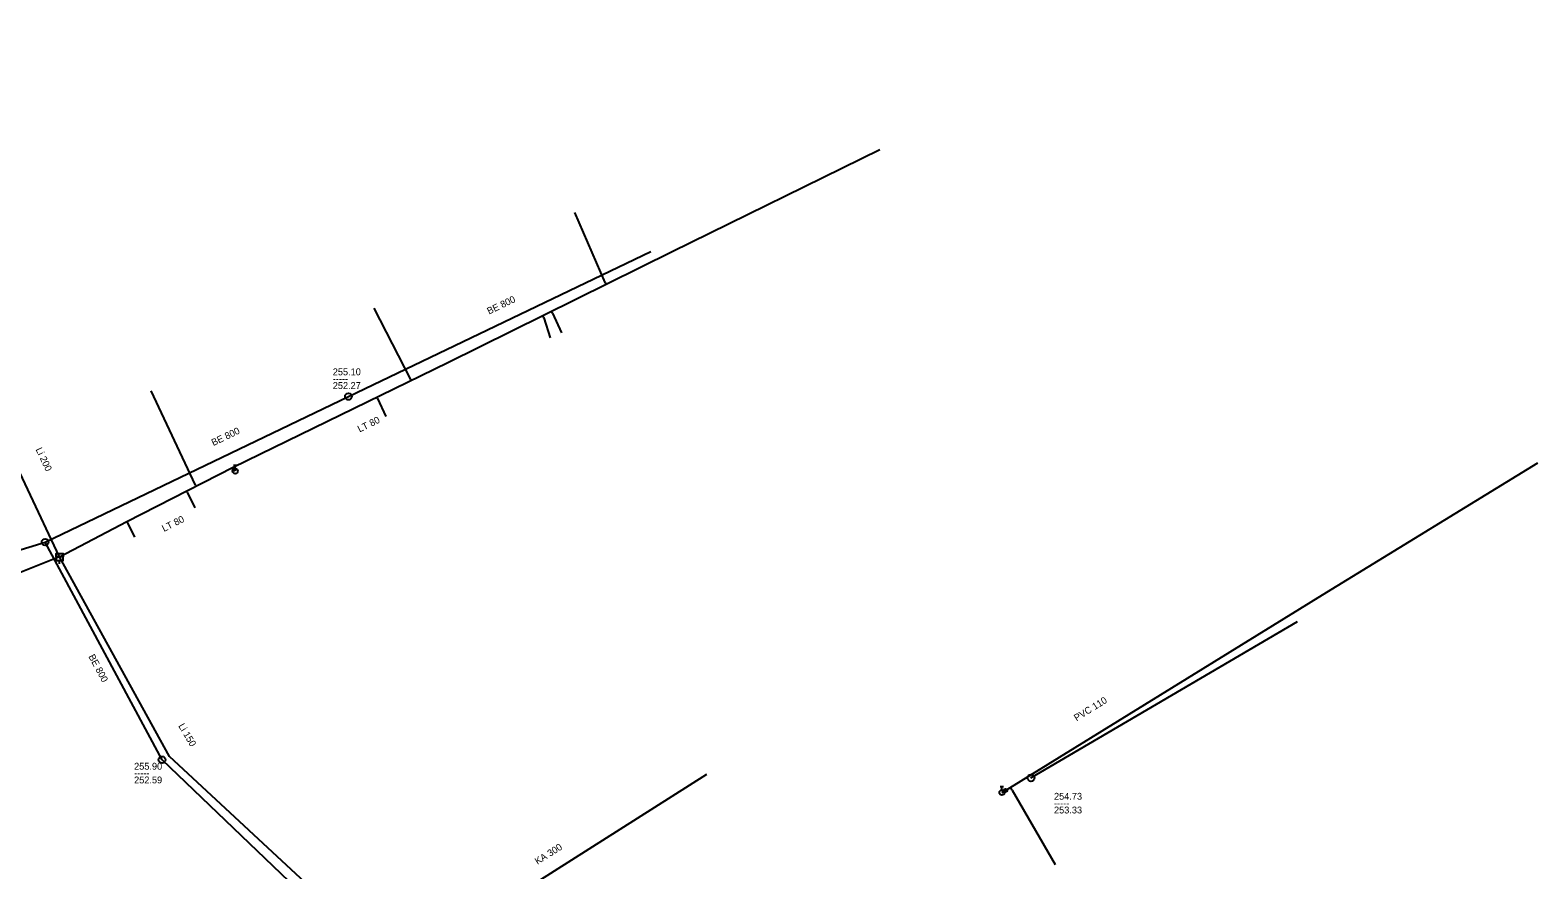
# Model space of a CAD drawing. Extents: x -647357 to -646700, y -1072205 to -1071664.
# Drawn here: x -647202.6 to -646982.9, y -1071786.5 to -1071664.1 of the extents above; entities that cross this region are included whole.
import ezdxf

# ---------------------------------------------------------------- set-up
doc = ezdxf.new("R2010")
doc.units = 0
for name, color, linetype in [('Level 19', 7, 'Continuous'), ('Level 20', 7, 'Continuous'), ('Level 21', 7, 'Continuous'), ('Level 24', 7, 'Continuous'), ('Level 26', 7, 'Continuous'), ('Level 29', 7, 'Continuous'), ('Level 40', 7, 'Continuous'), ('Level 41', 7, 'Continuous'), ('Level 44', 7, 'Continuous')]:
    doc.layers.add(name, color=color, linetype=linetype)

msp = doc.modelspace()

# ---------------------------------------------------------------- linework, layer by layer
at = {"layer": 'Level 19'}
for p, q in [((-647118.84, -1071700.88), (-647123.24, -1071690.68)), ((-647118.84, -1071700.88), (-647118.71, -1071701.14)), ((-647147.15, -1071715.02), (-647152.5, -1071704.62)), ((-647127.76, -1071706.02), (-647127.92, -1071705.69)), ((-647127.76, -1071706.02), (-647126.83, -1071708.93)), ((-647126.51, -1071705.32), (-647126.64, -1071705.06)), ((-647126.51, -1071705.32), (-647125.18, -1071708.2)), ((-647147.15, -1071715.02), (-647147.09, -1071715.13)), ((-647178.53, -1071730.43), (-647184.98, -1071716.68)), ((-647151.99, -1071717.79), (-647152.09, -1071717.58)), ((-647151.99, -1071717.79), (-647150.77, -1071720.42)), ((-647178.53, -1071730.43), (-647178.46, -1071730.57)), ((-647179.76, -1071731.43), (-647179.84, -1071731.27)), ((-647179.76, -1071731.43), (-647178.64, -1071733.73)), ((-647188.55, -1071735.7), (-647187.44, -1071738)), ((-647059.47, -1071774.88), (-647059.73, -1071774.45)), ((-647059.47, -1071774.88), (-647053.2, -1071785.7))]:
    msp.add_line(p, q, dxfattribs=at)
at = {"layer": 'Level 20'}
for p, q in [((-647198.35, -1071740.88), (-647234.6, -1071664.09)), ((-647109.04, -1071696.36), (-647078.76, -1071681.49)), ((-647141.77, -1071712.54), (-647109.04, -1071696.36)), ((-647173.04, -1071727.8), (-647141.77, -1071712.54)), ((-647188.54, -1071735.72), (-647173.04, -1071727.8)), ((-647173.04, -1071727.8), (-647172.91, -1071728.05)), ((-647172.91, -1071728.05), (-647172.75, -1071728.37)), ((-647013.6, -1071746.01), (-646982.86, -1071727.14)), ((-647198.35, -1071740.88), (-647188.54, -1071735.72)), ((-647198.35, -1071740.88), (-647263.8, -1071766.64)), ((-647182.34, -1071769.97), (-647198.35, -1071740.88)), ((-647060.46, -1071774.9), (-647013.6, -1071746.01)), ((-647148.55, -1071801.29), (-647182.34, -1071769.97)), ((-647060.98, -1071775.22), (-647060.46, -1071774.9))]:
    msp.add_line(p, q, dxfattribs=at)
at = {"layer": 'Level 21'}
for p, q in [((-647173, -1071727.495), (-647172.5, -1071727.495)), ((-647172.75, -1071727.995), (-647172.75, -1071727.495)), ((-647061.23, -1071774.345), (-647060.73, -1071774.345)), ((-647060.98, -1071774.845), (-647060.98, -1071774.345))]:
    msp.add_line(p, q, dxfattribs=at)
for centre in [(-647172.75, -1071728.37), (-647060.98, -1071775.22)]:
    msp.add_circle(centre, 0.375, dxfattribs=at)
at = {"layer": 'Level 26'}
for centre in [(-647172.91, -1071728.05), (-647060.46, -1071774.9)]:
    msp.add_circle(centre, 0.25, dxfattribs=at)
at = {"layer": 'Level 29'}
msp.add_line((-647198.35, -1071741.88), (-647198.35, -1071741.38), dxfattribs=at)
msp.add_lwpolyline([(-647198.85, -1071740.88), (-647198.85, -1071740.38), (-647197.85, -1071740.38), (-647197.85, -1071740.88)], dxfattribs=at)
msp.add_lwpolyline([(-647198.85, -1071741.38), (-647197.85, -1071741.38), (-647197.85, -1071740.88), (-647198.85, -1071740.88)], close=True, dxfattribs=at)
at = {"layer": 'Level 40'}
for p, q in [((-647156.24, -1071717.49), (-647112.15, -1071696.37)), ((-647200.46, -1071738.72), (-647156.24, -1071717.49)), ((-647216.4, -1071743.58), (-647200.46, -1071738.72)), ((-647183.42, -1071770.44), (-647200.46, -1071738.72)), ((-647056.75, -1071773.08), (-647017.92, -1071750.26)), ((-647150.45, -1071801.98), (-647183.42, -1071770.44)), ((-647104.07, -1071772.57), (-647150.45, -1071801.98))]:
    msp.add_line(p, q, dxfattribs=at)
at = {"layer": 'Level 41'}
for centre in [(-647156.24, -1071717.49), (-647200.46, -1071738.72), (-647183.42, -1071770.44), (-647056.75, -1071773.08)]:
    msp.add_circle(centre, 0.5, dxfattribs=at)

# ---------------------------------------------------------------- texts
at = {"layer": 'Level 24'}
for s, rotation, p in [('LT 80', 26.305, (-647154.62, -1071722.75)), ('Li 200', 295.27, (-647201.87, -1071725.2)), ('LT 80', 27.066, (-647183.12, -1071737.24)), ('PVC 110', 31.686, (-647050.1, -1071764.85)), ('Li 150', 300.733, (-647181.09, -1071765.5))]:
    msp.add_text(s, height=1, rotation=rotation, dxfattribs=at).set_placement(p)
at = {"layer": 'Level 44'}
for s, rotation, p in [('BE 800', 25.595, (-647135.75, -1071705.55)), ('BE 800', 25.646, (-647175.93, -1071724.72)), ('BE 800', 298.245, (-647194.18, -1071755.38)), ('KA 300', 32.379, (-647128.68, -1071785.76))]:
    msp.add_text(s, height=1, rotation=rotation, dxfattribs=at).set_placement(p)
for s, p in [('-----', (-647158.53, -1071715.39)), ('255.10', (-647158.53, -1071714.39)), ('252.27', (-647158.53, -1071716.39)), ('255.90', (-647187.49, -1071771.88)), ('-----', (-647187.49, -1071772.88)), ('252.59', (-647187.49, -1071773.88)), ('-----', (-647053.39, -1071777.26)), ('254.73', (-647053.39, -1071776.26)), ('253.33', (-647053.39, -1071778.26))]:
    msp.add_text(s, height=1, dxfattribs=at).set_placement(p)

doc.saveas('drawing.dxf')
